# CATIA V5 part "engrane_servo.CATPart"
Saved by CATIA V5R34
Part number: engrane_servo
Bounding box of the stored display mesh (mm): x -12.913 to 12.913, y -12.464 to 13, z 0 to 8
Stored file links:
  C:\Users\Apolinar\Desktop\cnc\engrane_servo.CATPart
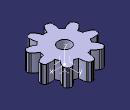
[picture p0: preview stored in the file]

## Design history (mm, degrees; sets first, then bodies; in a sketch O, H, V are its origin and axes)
AxisSystem1: origin (0, 0, 0), X (1, 0, 0), Y (0, 1, 0), Z (0, 0, 1)
Body1 (main body)
  Sketch1 on XY plane of AxisSystem1, origin (0, 0, 0), H (1, 0, 0), V (0, 1, 0)
    arc A1 centre (0, 0) radius 2.9 from (0.9919, 2.7251) to (-0.9919, 2.7251) ccw
    arc A2 centre (0, 0) radius 9 from (-2.1732, 8.7337) to (-3.0782, 8.4572) ccw
    line L1 (-1.25, 13) -> (0, 13)
    point P1 (-1.25, 13)
    point P2 (-0.5, 8.9861)
    ellipse A3 centre (-0.5, 8.9861) semi-axes 4.0139, 1.6755 rotation 89.734 from (-1.7109, 11.7337) to (-2.1732, 8.7337)
    construction line L2 (0, 18.7711) -> (0, 13)
    point P4 (0, 13)
    line L3 (-1.25, 13) -> (-1.7109, 11.7337)
    point P5 (-1.7109, 11.7337)
    point P6 (-1.7109, 11.7337)
    point P7 (-2.1732, 8.7337)
    point P8 (1.25, 13)
    point P9 (0, 13)
    line L4 (1.25, 13) -> (0, 13)
    point P10 (2.1732, 8.7337)
    point P11 (1.7109, 11.7337)
    ellipse A4 centre (0.5, 8.9861) semi-axes 4.0139, 1.6755 rotation 90.266 from (1.7109, 11.7337) to (2.1732, 8.7337)
    point P13 (1.7109, 11.7337)
    line L5 (1.25, 13) -> (1.7109, 11.7337)
    line L6 (-3.0782, 8.4572) -> (-0.9919, 2.7251)
    line L7 (0.9919, 2.7251) -> (3.0782, 8.4572)
    point P15 (0, 0)
    point P16 (3.0782, 8.4572)
    construction line L8 (-2.1732, 8.7337) -> (0, 0)
    construction line L9 (0, 0) -> (2.1732, 8.7337)
    point P17 (2.1732, 8.7337)
    arc A5 centre (0, 0) radius 9 from (3.0782, 8.4572) to (2.1732, 8.7337) ccw
    construction line L10 (-0.9919, 2.7251) -> (0, 0)
    point P20 (-0.9919, 2.7251)
    axis line L11 (0, 0) -> (0.9919, 2.7251)
    radius A1 = 2.9
    distance A2 L1 = 4
    distance L2 P2 = 0.5
    length L1 = 1.25
    angle L3 L1 = 110
    angle A3 A4 = 0.532
    distance P5 P7 V = 3
    radius A2 = 9
    angle L8 L9 = 27.9456 (reference)
    angle L6 L7 = 40
    angle L6 V = 20
    horizontal: L1 H
    coincidence: P2 A2, L2 V, P5 A3, L3 P6, P15 L6, P15 V, P16 A2, P17 A2, L9 P10, A2 A5, P4 P9, P5 P6, P11 P13, P20 A1, L6 L10, P15 H, L11 L7
    tangency: L1 A3
    vertical: L2 V
    symmetry: P1 P8 V, P4 P9 V, L1 L4 V, P7 P10 V, P6 P11 V, A3 A4 V, P5 P13 V, L3 L5 V
  Pad1: profile Sketch1, direction (0, 0, 1), length 8
  Fillet1: radius 1, on edge [face of Pad1 from Sketch1.L4 | face of Pad1 from Sketch1.L5]; edge [face of Pad1 from Sketch1.L3 | face of Pad1 from Sketch1.L1]
  CircPattern1: of the body so far, instances 9, angular step 40 {= 360.0*1 deg/CircPattern1.AngularNumber}, axis from XY plane of AxisSystem1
